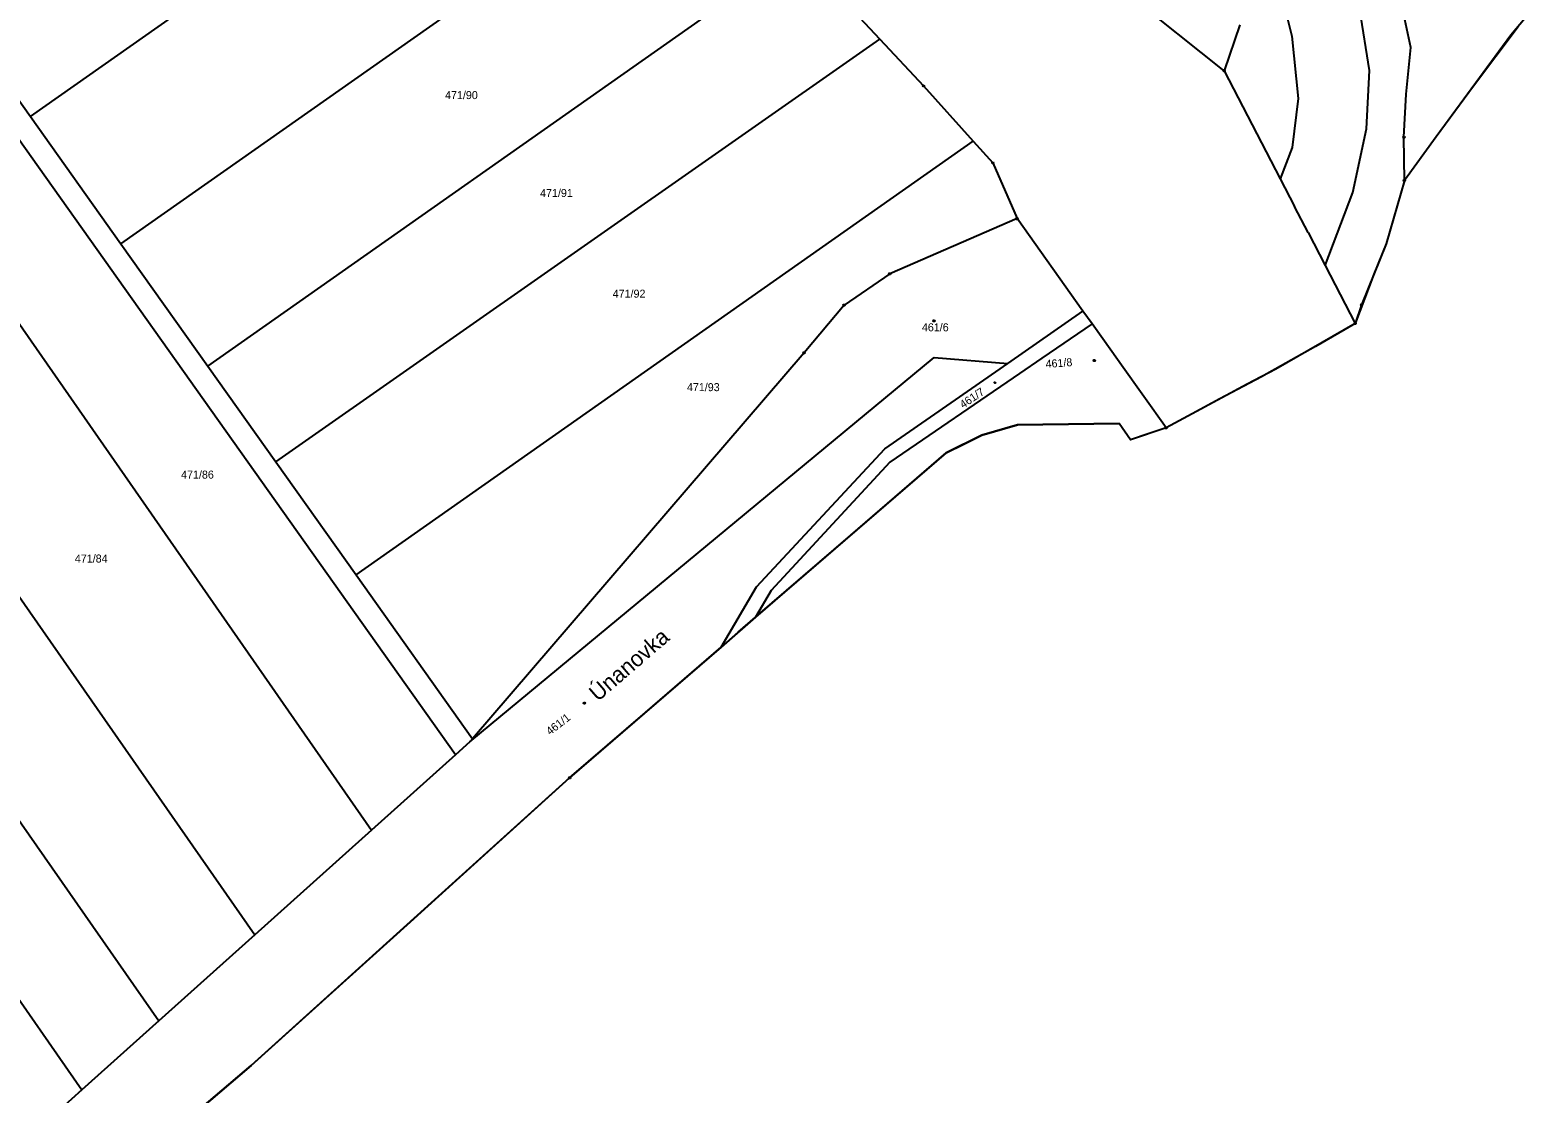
# Model space of a CAD drawing. Extents: x -634640 to -629202, y -1196156 to -1190068.
# Drawn here: x -630498.3 to -630180.7, y -1192515.9 to -1192290.2 of the extents above; entities that cross this region are included whole.
import ezdxf

# ---------------------------------------------------------------- set-up
doc = ezdxf.new("R2010")
doc.units = 0
for name, color, linetype in [('Obvod převzatý', 7, 'Continuous'), ('Vrstva 1', 7, 'Continuous'), ('Vrstva 2', 7, 'Continuous'), ('Vrstva 3', 7, 'Continuous'), ('Vrstva 7', 7, 'Continuous'), ('Vrstva 8', 7, 'Continuous')]:
    doc.layers.add(name, color=color, linetype=linetype)

msp = doc.modelspace()

# ---------------------------------------------------------------- linework, layer by layer
at = {"layer": 'Obvod převzatý'}
for points in [[(-630182.155, -1192289.47), (-630191.595, -1192302.08), (-630199.53, -1192312.89), (-630206.3, -1192322.11), (-630210.16, -1192335.56), (-630212.78, -1192342.04), (-630216.75, -1192352.51), (-630225.17, -1192357.36), (-630236.635, -1192363.8), (-630245.535, -1192368.535), (-630251.39, -1192371.68), (-630256.93, -1192374.65), (-630260.72, -1192375.935), (-630264.51, -1192377.22), (-630266.87, -1192373.72)], [(-630489.17, -1192542.285), (-630451.28, -1192510.07), (-630417.46, -1192479.53), (-630383.64, -1192448.99), (-630367.56, -1192435.11), (-630351.48, -1192421.23), (-630347.835, -1192418.065), (-630344.19, -1192414.9), (-630323.935, -1192397.425), (-630303.68, -1192379.95), (-630299.88, -1192378.1), (-630296.08, -1192376.25), (-630288.48, -1192374.04), (-630277.675, -1192373.88), (-630266.87, -1192373.72)]]:
    msp.add_lwpolyline(points, dxfattribs=at)
at = {"layer": 'Vrstva 1'}
for p, q in [((-630498.21, -1192308.54), (-630379.97, -1192225.45)), ((-630478.98, -1192335.6), (-630357.1, -1192249.95)), ((-630244.59, -1192298.82), (-630294.17, -1192259.26)), ((-630460.53, -1192361.56), (-630335.15, -1192273.45)), ((-630335.15, -1192273.45), (-630317.74, -1192292.11)), ((-630204.91, -1192293.9), (-630208.37, -1192277.72)), ((-630518.39, -1192280.14), (-630498.21, -1192308.54)), ((-630233.19, -1192279.42), (-630230.2, -1192291.48)), ((-630213.68, -1192298.8), (-630215.77, -1192285.86)), ((-630180.65, -1192287.67), (-630183.66, -1192291.27)), ((-630241.25, -1192289.05), (-630244.59, -1192298.82)), ((-630230.2, -1192291.48), (-630228.86, -1192304.73)), ((-630183.66, -1192291.27), (-630199.53, -1192312.89)), ((-630446.1, -1192381.87), (-630317.74, -1192292.11)), ((-630317.74, -1192292.11), (-630308.46, -1192302.04)), ((-630205.9, -1192303.78), (-630204.91, -1192293.9)), ((-630407.87, -1192444.07), (-630509.49, -1192301.05)), ((-630244.59, -1192298.82), (-630232.7, -1192321.75)), ((-630214.31, -1192311.13), (-630213.68, -1192298.8)), ((-630308.46, -1192302.04), (-630297.9, -1192313.75)), ((-630228.86, -1192304.73), (-630230.11, -1192315.11)), ((-630206.39, -1192312.94), (-630205.9, -1192303.78)), ((-630531.77, -1192307.81), (-630425.74, -1192460.09)), ((-630498.21, -1192308.54), (-630478.98, -1192335.6)), ((-630429.02, -1192405.9), (-630297.9, -1192313.75)), ((-630297.9, -1192313.75), (-630293.74, -1192318.36)), ((-630217.25, -1192324.7), (-630214.31, -1192311.13)), ((-630206.3, -1192322.11), (-630206.39, -1192312.94)), ((-630199.53, -1192312.89), (-630206.3, -1192322.11)), ((-630230.11, -1192315.11), (-630232.7, -1192321.75)), ((-630293.74, -1192318.36), (-630288.58, -1192330.24)), ((-630232.7, -1192321.75), (-630229.62, -1192327.69)), ((-630206.3, -1192322.11), (-630210.16, -1192335.56)), ((-630559, -1192326.87), (-630450.52, -1192482.31)), ((-630223.12, -1192340.21), (-630217.25, -1192324.7)), ((-630226.77, -1192333.18), (-630229.62, -1192327.69)), ((-630288.58, -1192330.24), (-630315.64, -1192341.96)), ((-630274.59, -1192349.87), (-630288.58, -1192330.24)), ((-630226.77, -1192333.18), (-630223.12, -1192340.21)), ((-630478.98, -1192335.6), (-630460.53, -1192361.56)), ((-630210.16, -1192335.56), (-630215.4, -1192348.52)), ((-630581.34, -1192342.52), (-630470.92, -1192500.6)), ((-630315.64, -1192341.96), (-630325.34, -1192348.63)), ((-630223.12, -1192340.21), (-630216.75, -1192352.51)), ((-630325.34, -1192348.63), (-630333.84, -1192358.73)), ((-630215.4, -1192348.52), (-630216.75, -1192352.51)), ((-630290.56, -1192360.98), (-630274.59, -1192349.87)), ((-630272.65, -1192352.58), (-630274.59, -1192349.87)), ((-630598.93, -1192354.86), (-630487.26, -1192515.25)), ((-630272.65, -1192352.58), (-630283.33, -1192359.89)), ((-630268.46, -1192358.46), (-630272.65, -1192352.58)), ((-630216.75, -1192352.51), (-630233.59, -1192362.21)), ((-630333.84, -1192358.73), (-630404.29, -1192440.71)), ((-630266.42, -1192361.33), (-630268.46, -1192358.46)), ((-630460.53, -1192361.56), (-630446.1, -1192381.87)), ((-630404.84, -1192441.35), (-630306.18, -1192359.73)), ((-630306.18, -1192359.73), (-630290.56, -1192360.98)), ((-630298.19, -1192366.28), (-630290.56, -1192360.98)), ((-630283.33, -1192359.89), (-630288.06, -1192363.13)), ((-630256.93, -1192374.65), (-630266.42, -1192361.33)), ((-630288.06, -1192363.13), (-630315.62, -1192381.96)), ((-630233.59, -1192362.21), (-630239.68, -1192365.39)), ((-630316.7, -1192379.14), (-630298.19, -1192366.28)), ((-630239.68, -1192365.39), (-630251.39, -1192371.68)), ((-630288.48, -1192374.04), (-630296.08, -1192376.25)), ((-630266.87, -1192373.72), (-630288.48, -1192374.04)), ((-630264.51, -1192377.22), (-630266.87, -1192373.72)), ((-630251.39, -1192371.68), (-630256.93, -1192374.65)), ((-630296.08, -1192376.25), (-630303.68, -1192379.95)), ((-630256.93, -1192374.65), (-630264.51, -1192377.22)), ((-630303.68, -1192379.95), (-630344.19, -1192414.9)), ((-630343.96, -1192408.4), (-630316.7, -1192379.14)), ((-630446.1, -1192381.87), (-630429.02, -1192405.9)), ((-630315.62, -1192381.96), (-630340.8, -1192409.23)), ((-630429.02, -1192405.9), (-630404.29, -1192440.71)), ((-630351.48, -1192421.23), (-630343.96, -1192408.4)), ((-630340.8, -1192409.23), (-630344.19, -1192414.9)), ((-630344.19, -1192414.9), (-630351.48, -1192421.23)), ((-630351.48, -1192421.23), (-630383.64, -1192448.99)), ((-630404.29, -1192440.71), (-630404.84, -1192441.35)), ((-630407.87, -1192444.07), (-630425.74, -1192460.09)), ((-630404.84, -1192441.35), (-630407.87, -1192444.07)), ((-630383.64, -1192448.99), (-630451.28, -1192510.07)), ((-630425.74, -1192460.09), (-630450.52, -1192482.31)), ((-630450.52, -1192482.31), (-630470.92, -1192500.6)), ((-630470.92, -1192500.6), (-630487.26, -1192515.25)), ((-630451.28, -1192510.07), (-630527.06, -1192574.5)), ((-630487.26, -1192515.25), (-630497.06, -1192524.04))]:
    msp.add_line(p, q, dxfattribs=at)
at = {"layer": 'Vrstva 3'}
for points in [[(-630306.13, -1192351.81), (-630306.04, -1192351.96), (-630306.13, -1192352.11), (-630306.31, -1192352.11), (-630306.4, -1192351.96), (-630306.31, -1192351.81), (-630306.13, -1192351.81)], [(-630272.088, -1192360.196), (-630271.99, -1192360.341), (-630272.072, -1192360.495), (-630272.252, -1192360.504), (-630272.35, -1192360.359), (-630272.268, -1192360.205), (-630272.088, -1192360.196)], [(-630293.26, -1192364.957), (-630293.174, -1192365.036), (-630293.204, -1192365.149), (-630293.32, -1192365.183), (-630293.406, -1192365.104), (-630293.376, -1192364.991), (-630293.26, -1192364.957)], [(-630380.571, -1192432.938), (-630380.404, -1192432.992), (-630380.374, -1192433.164), (-630380.509, -1192433.282), (-630380.676, -1192433.228), (-630380.706, -1192433.056), (-630380.571, -1192432.938)]]:
    msp.add_lwpolyline(points, dxfattribs=at)
at = {"layer": 'Vrstva 8'}
for points in [[(-630244.5, -1192298.67), (-630244.41, -1192298.82), (-630244.5, -1192298.97), (-630244.68, -1192298.97), (-630244.77, -1192298.82), (-630244.68, -1192298.67), (-630244.5, -1192298.67)], [(-630308.37, -1192301.89), (-630308.28, -1192302.04), (-630308.37, -1192302.19), (-630308.55, -1192302.19), (-630308.64, -1192302.04), (-630308.55, -1192301.89), (-630308.37, -1192301.89)], [(-630206.3, -1192312.79), (-630206.21, -1192312.94), (-630206.3, -1192313.09), (-630206.48, -1192313.09), (-630206.57, -1192312.94), (-630206.48, -1192312.79), (-630206.3, -1192312.79)], [(-630293.65, -1192318.21), (-630293.56, -1192318.36), (-630293.65, -1192318.51), (-630293.83, -1192318.51), (-630293.92, -1192318.36), (-630293.83, -1192318.21), (-630293.65, -1192318.21)], [(-630206.21, -1192321.96), (-630206.12, -1192322.11), (-630206.21, -1192322.26), (-630206.39, -1192322.26), (-630206.48, -1192322.11), (-630206.39, -1192321.96), (-630206.21, -1192321.96)], [(-630288.49, -1192330.09), (-630288.4, -1192330.24), (-630288.49, -1192330.39), (-630288.67, -1192330.39), (-630288.76, -1192330.24), (-630288.67, -1192330.09), (-630288.49, -1192330.09)], [(-630315.55, -1192341.81), (-630315.46, -1192341.96), (-630315.55, -1192342.11), (-630315.73, -1192342.11), (-630315.82, -1192341.96), (-630315.73, -1192341.81), (-630315.55, -1192341.81)], [(-630325.25, -1192348.48), (-630325.16, -1192348.63), (-630325.25, -1192348.78), (-630325.43, -1192348.78), (-630325.52, -1192348.63), (-630325.43, -1192348.48), (-630325.25, -1192348.48)], [(-630215.31, -1192348.37), (-630215.22, -1192348.52), (-630215.31, -1192348.67), (-630215.49, -1192348.67), (-630215.58, -1192348.52), (-630215.49, -1192348.37), (-630215.31, -1192348.37)], [(-630216.66, -1192352.36), (-630216.57, -1192352.51), (-630216.66, -1192352.66), (-630216.84, -1192352.66), (-630216.93, -1192352.51), (-630216.84, -1192352.36), (-630216.66, -1192352.36)], [(-630333.75, -1192358.58), (-630333.66, -1192358.73), (-630333.75, -1192358.88), (-630333.93, -1192358.88), (-630334.02, -1192358.73), (-630333.93, -1192358.58), (-630333.75, -1192358.58)], [(-630256.84, -1192374.5), (-630256.75, -1192374.65), (-630256.84, -1192374.8), (-630257.02, -1192374.8), (-630257.11, -1192374.65), (-630257.02, -1192374.5), (-630256.84, -1192374.5)], [(-630383.55, -1192448.84), (-630383.46, -1192448.99), (-630383.55, -1192449.14), (-630383.73, -1192449.14), (-630383.82, -1192448.99), (-630383.73, -1192448.84), (-630383.55, -1192448.84)]]:
    msp.add_lwpolyline(points, dxfattribs=at)

# ---------------------------------------------------------------- texts
at = {"layer": 'Vrstva 2'}
for s, p in [('471/90', (-630410.113, -1192304.85)), ('471/91', (-630389.923, -1192325.64)), ('471/92', (-630374.493, -1192347.02)), ('461/6', (-630308.803, -1192354.16)), ('471/93', (-630358.723, -1192366.87)), ('471/86', (-630466.193, -1192385.44)), ('471/84', (-630488.763, -1192403.26))]:
    msp.add_text(s, height=1.7, dxfattribs=at).set_placement(p)
for s, rotation, p in [('461/8', 4.41178, (-630282.463, -1192361.972)), ('461/7', 34.20558, (-630300.044, -1192370.617))]:
    msp.add_text(s, height=1.7, rotation=rotation, dxfattribs=at).set_placement(p)
at = {"layer": 'Vrstva 7'}
for s, height, rotation, p in [('Únanovka', 3.4, 40.7373, (-630377.673, -1192432.917)), ('461/1', 1.7, 37.87251, (-630387.804, -1192440.007))]:
    msp.add_text(s, height=height, rotation=rotation, dxfattribs=at).set_placement(p)

doc.saveas('drawing.dxf')
